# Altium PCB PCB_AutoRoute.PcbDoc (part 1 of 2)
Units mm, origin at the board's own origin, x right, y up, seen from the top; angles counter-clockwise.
Board outline 100 x 100 mm, 4 copper layers (Top Layer, AGND, PWR, Bottom Layer), stack 1.747 mm thick; 183 components, 95 nets, 503 pads, 230 vias.
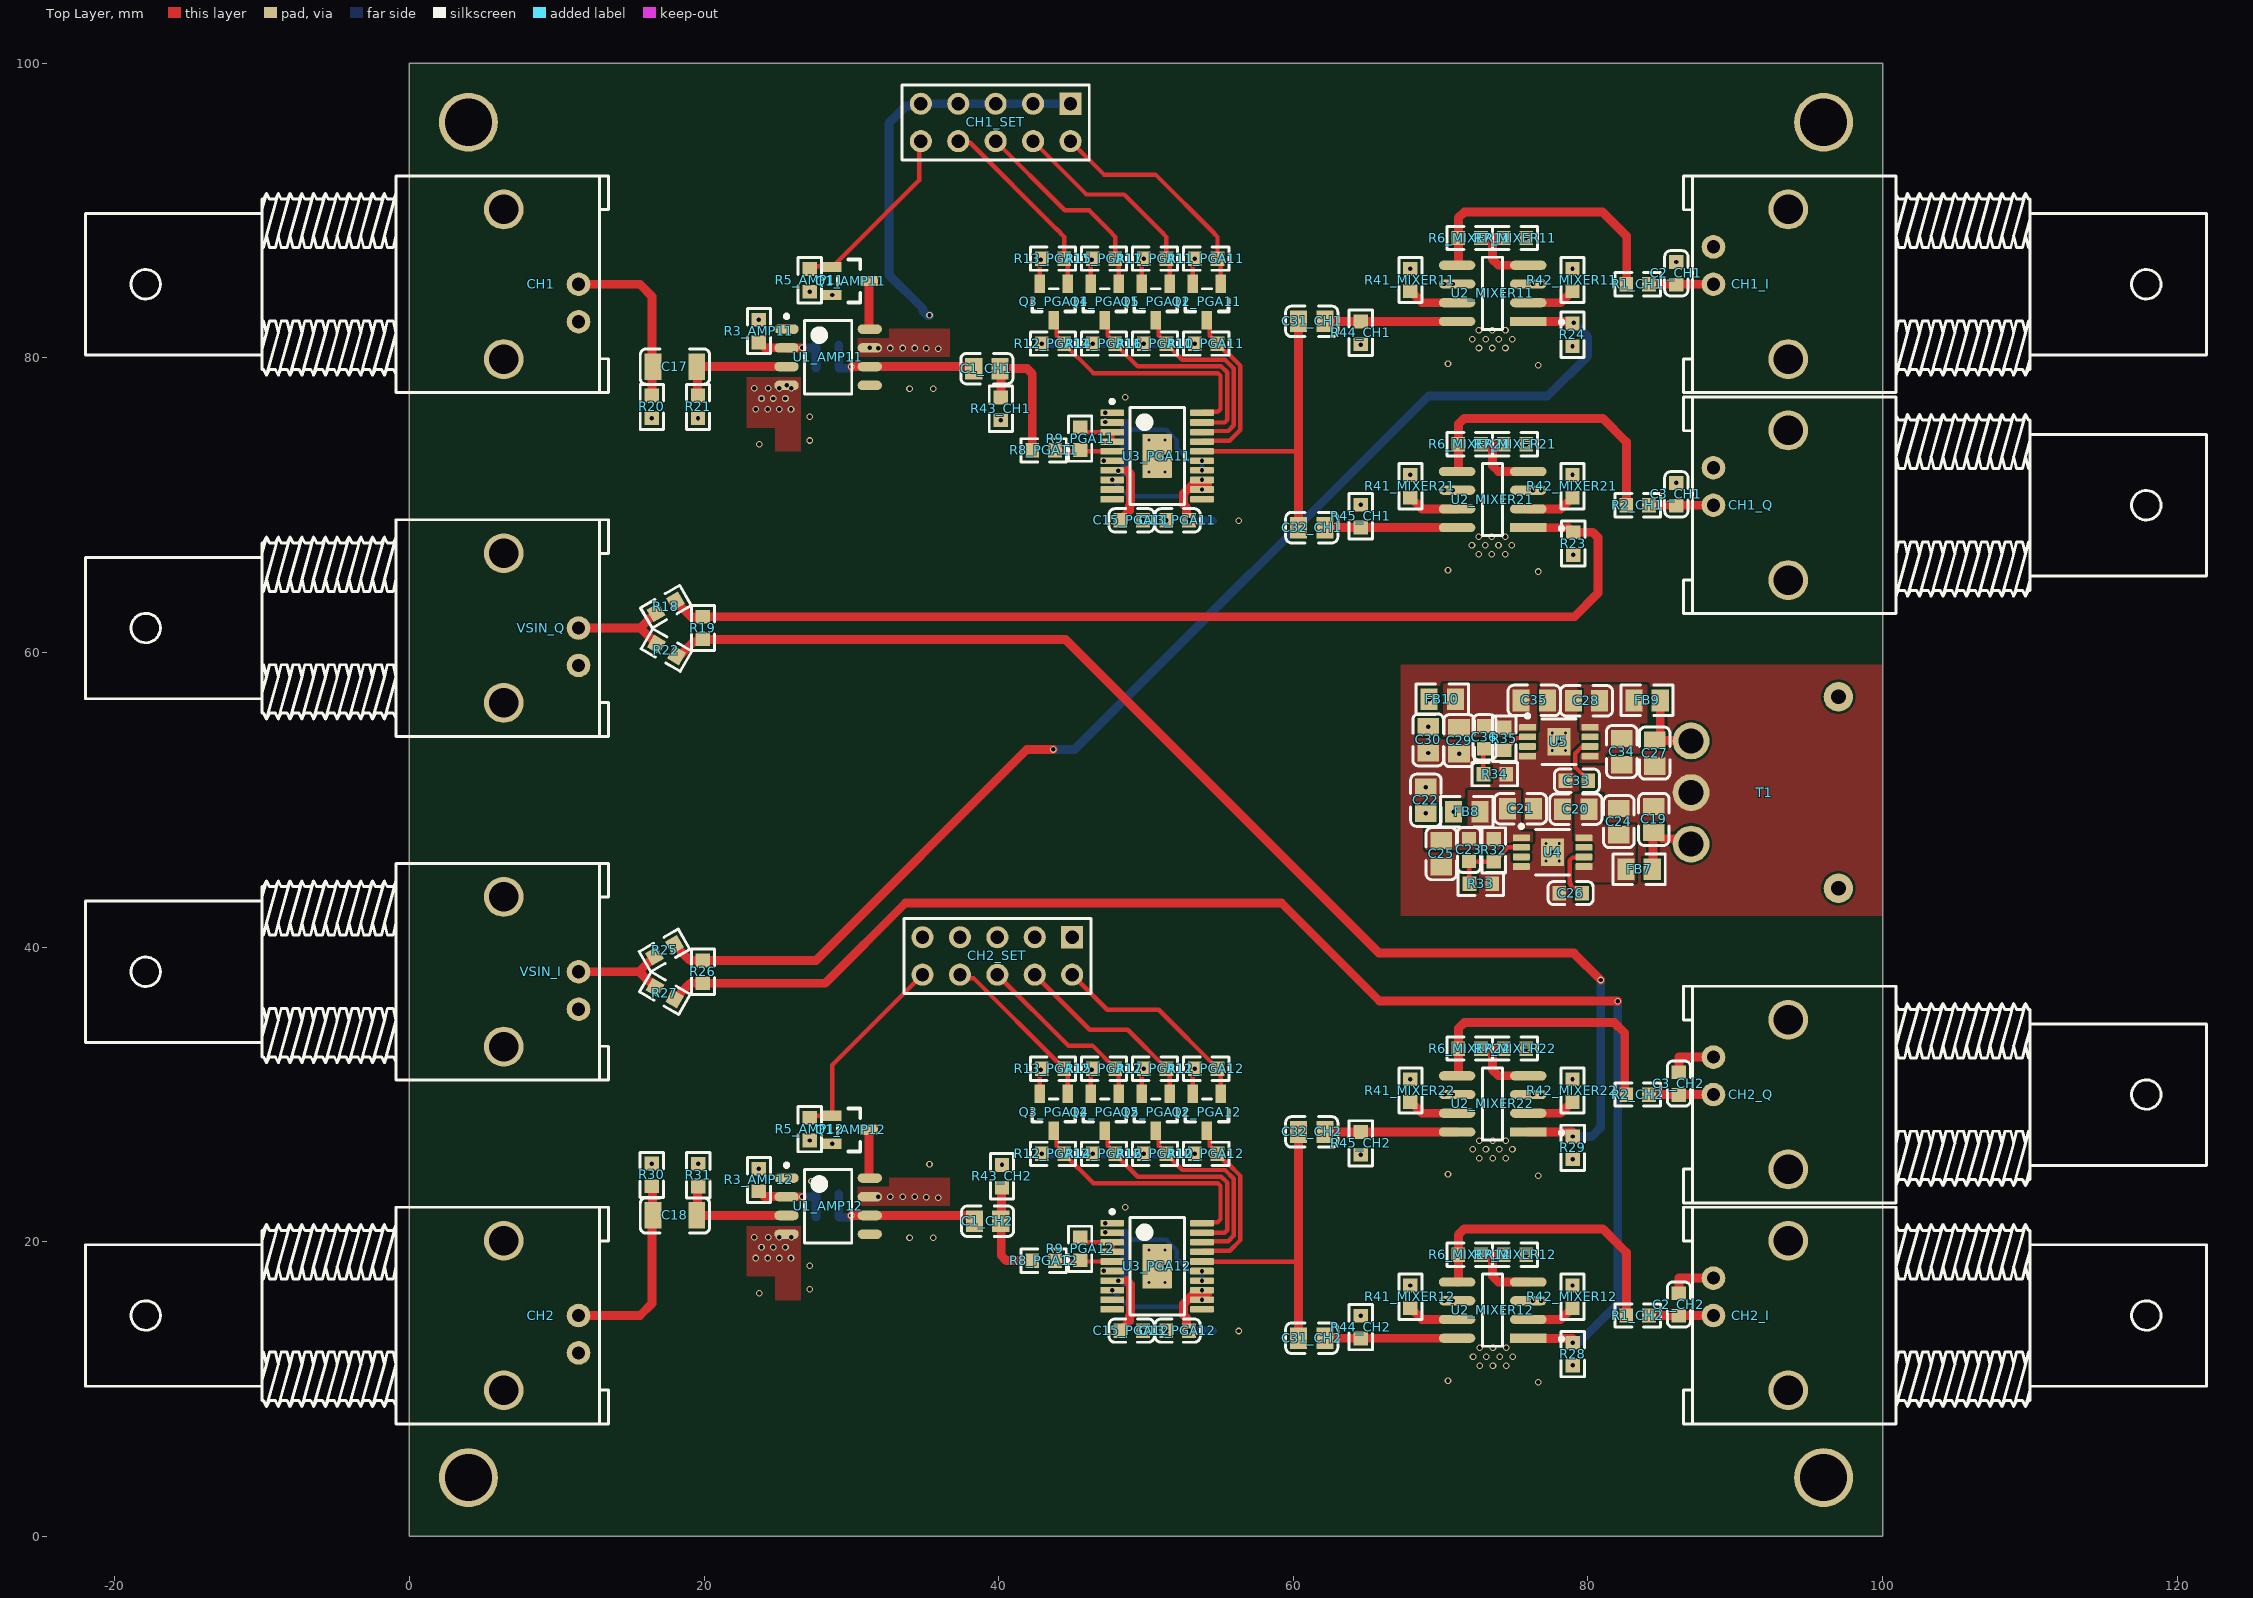
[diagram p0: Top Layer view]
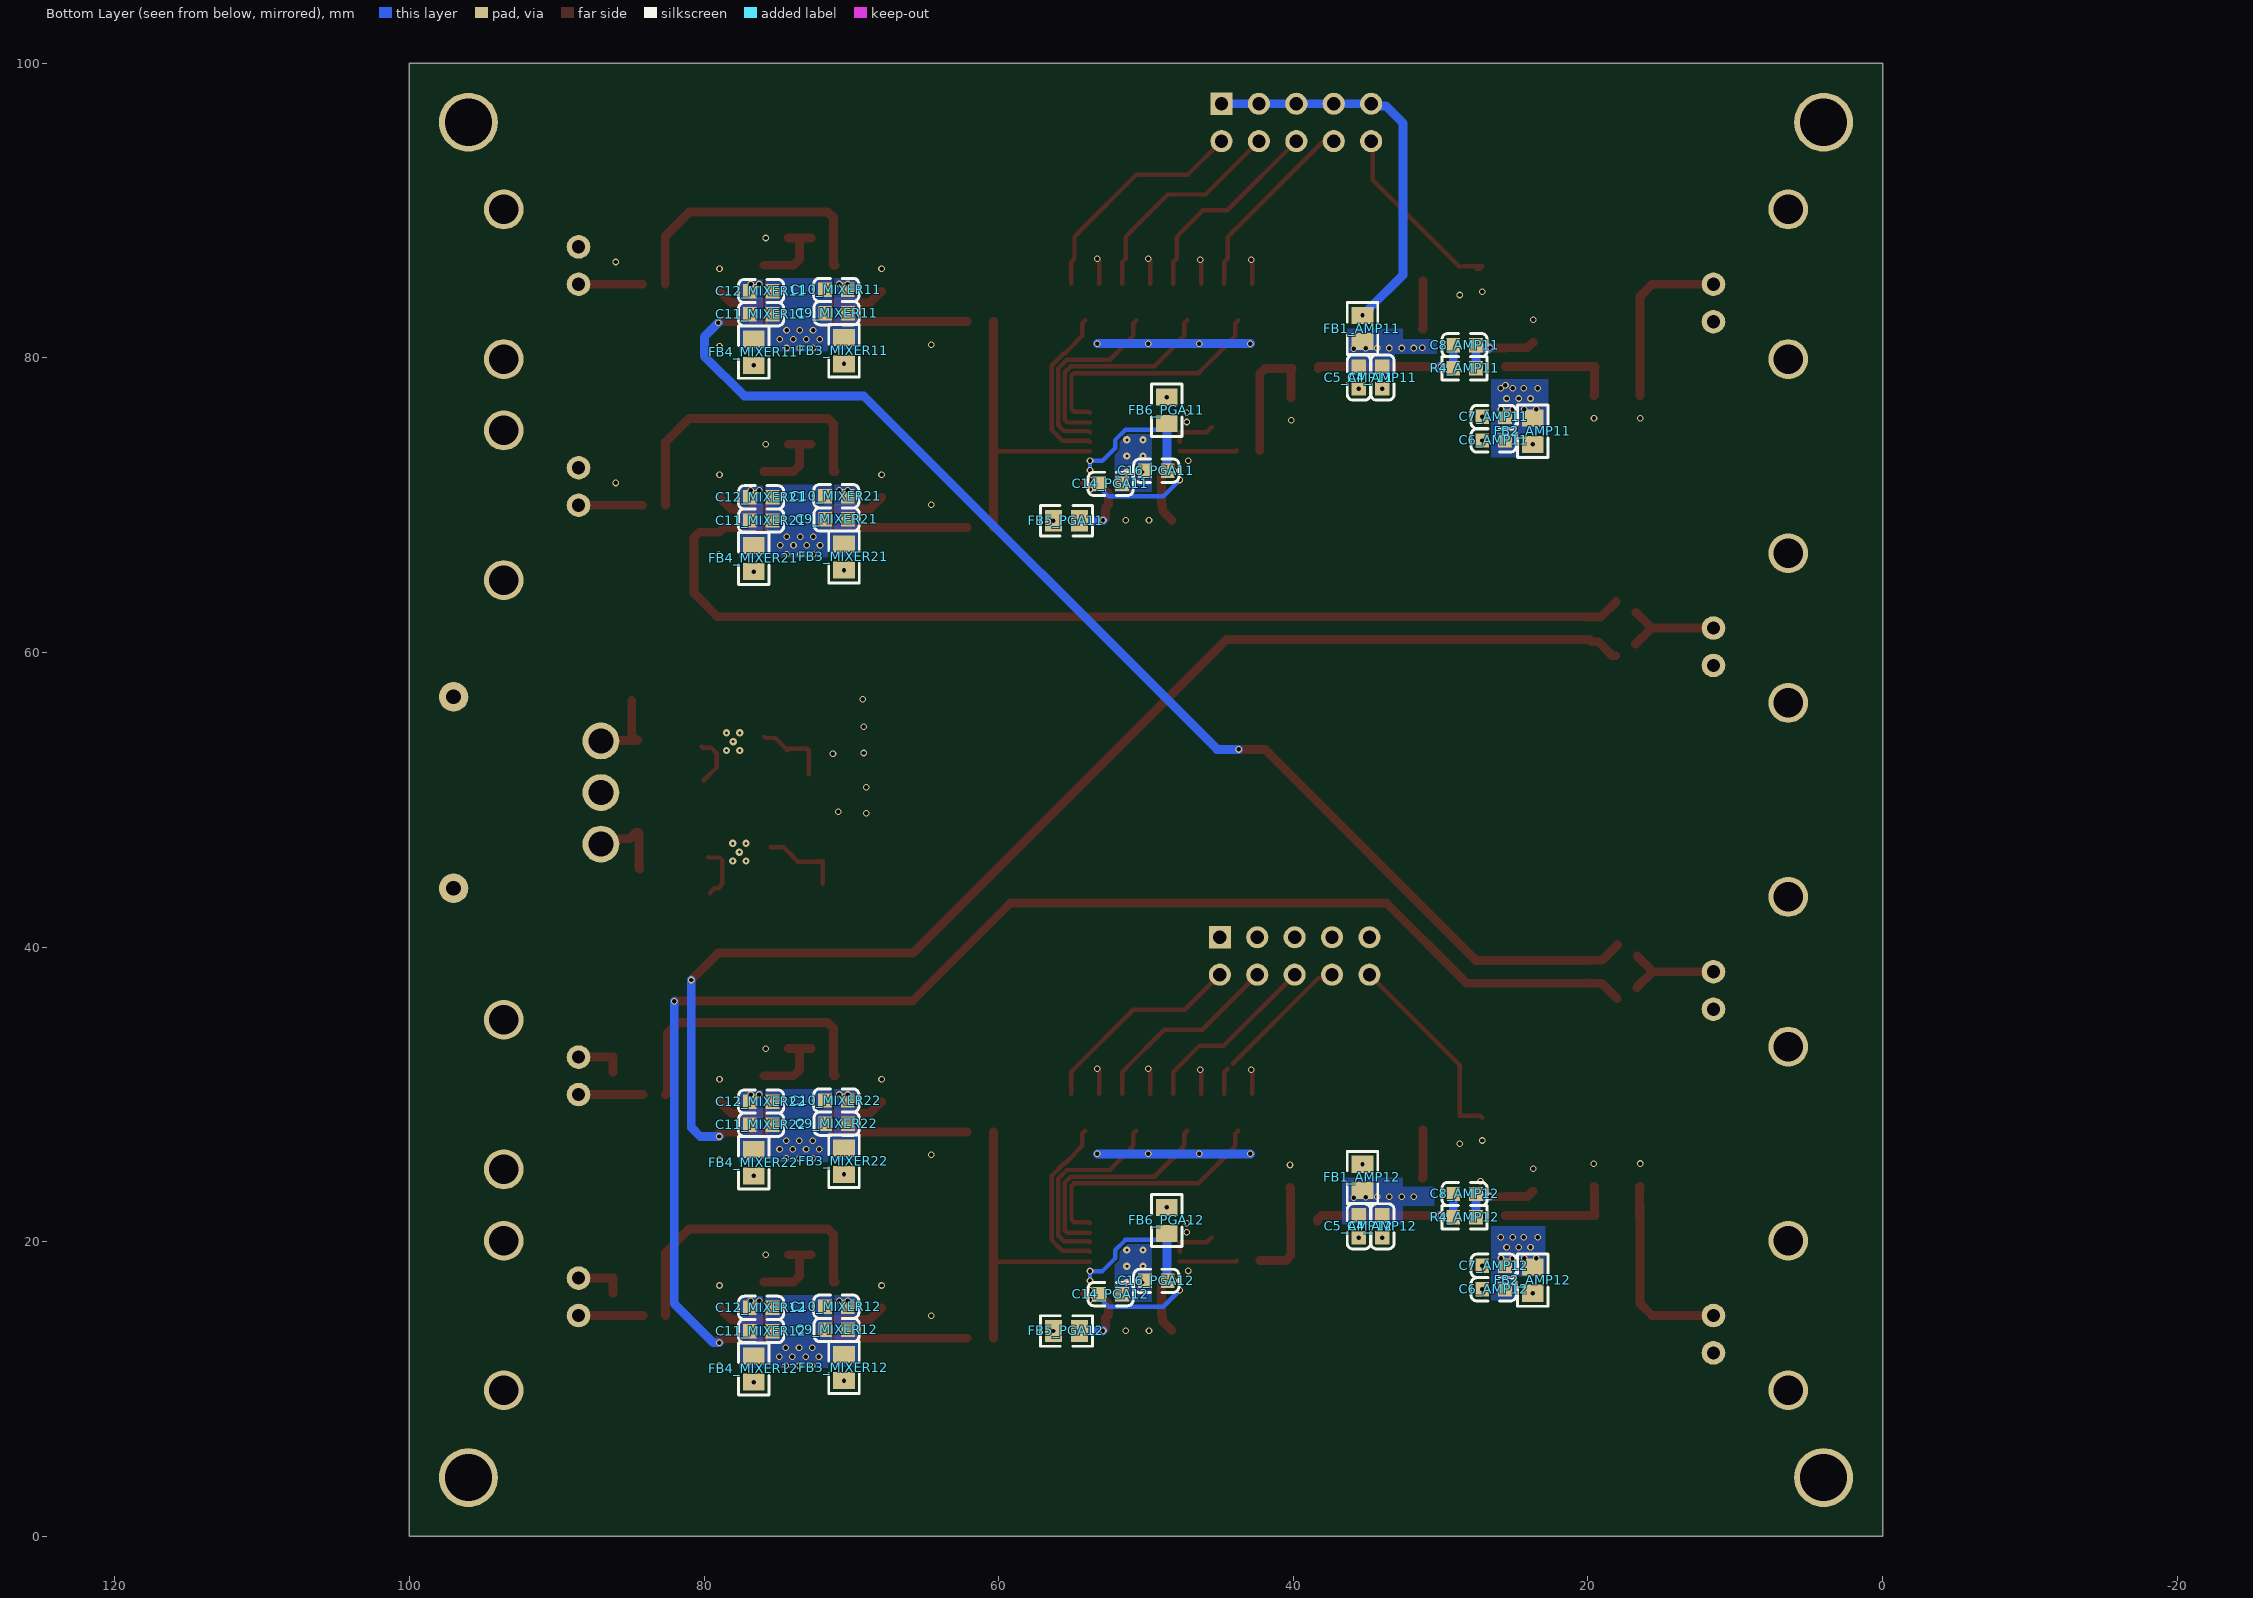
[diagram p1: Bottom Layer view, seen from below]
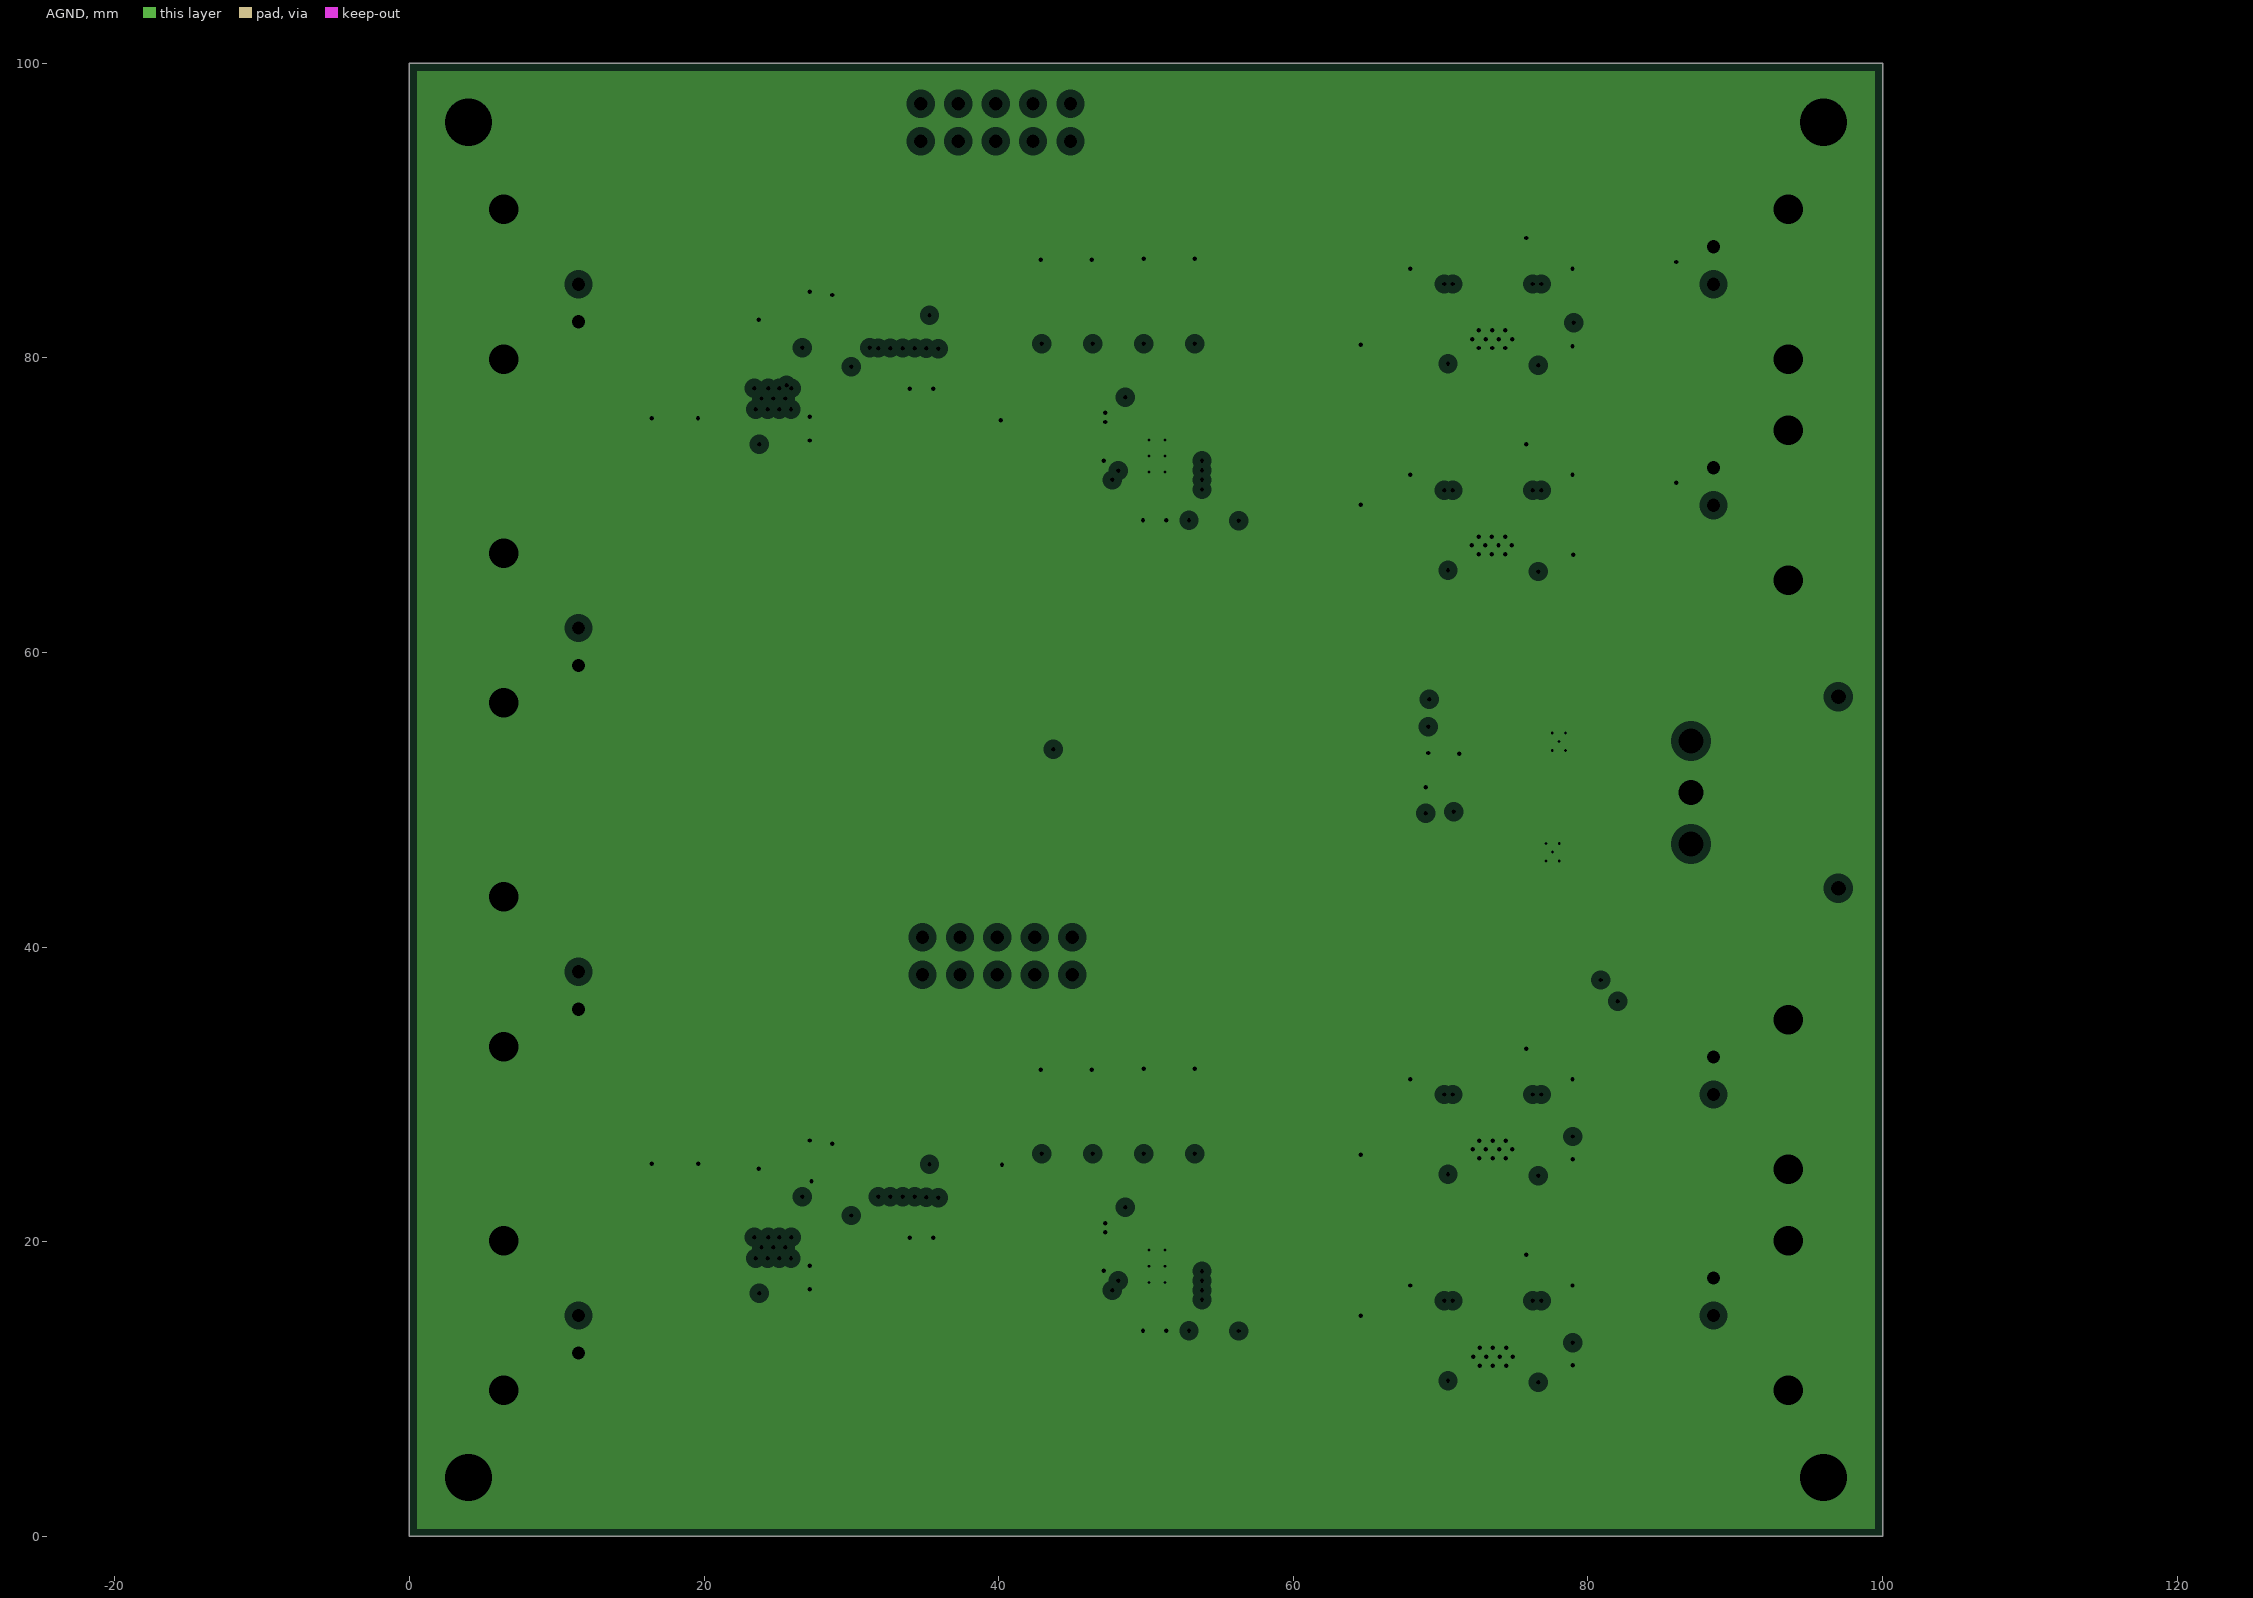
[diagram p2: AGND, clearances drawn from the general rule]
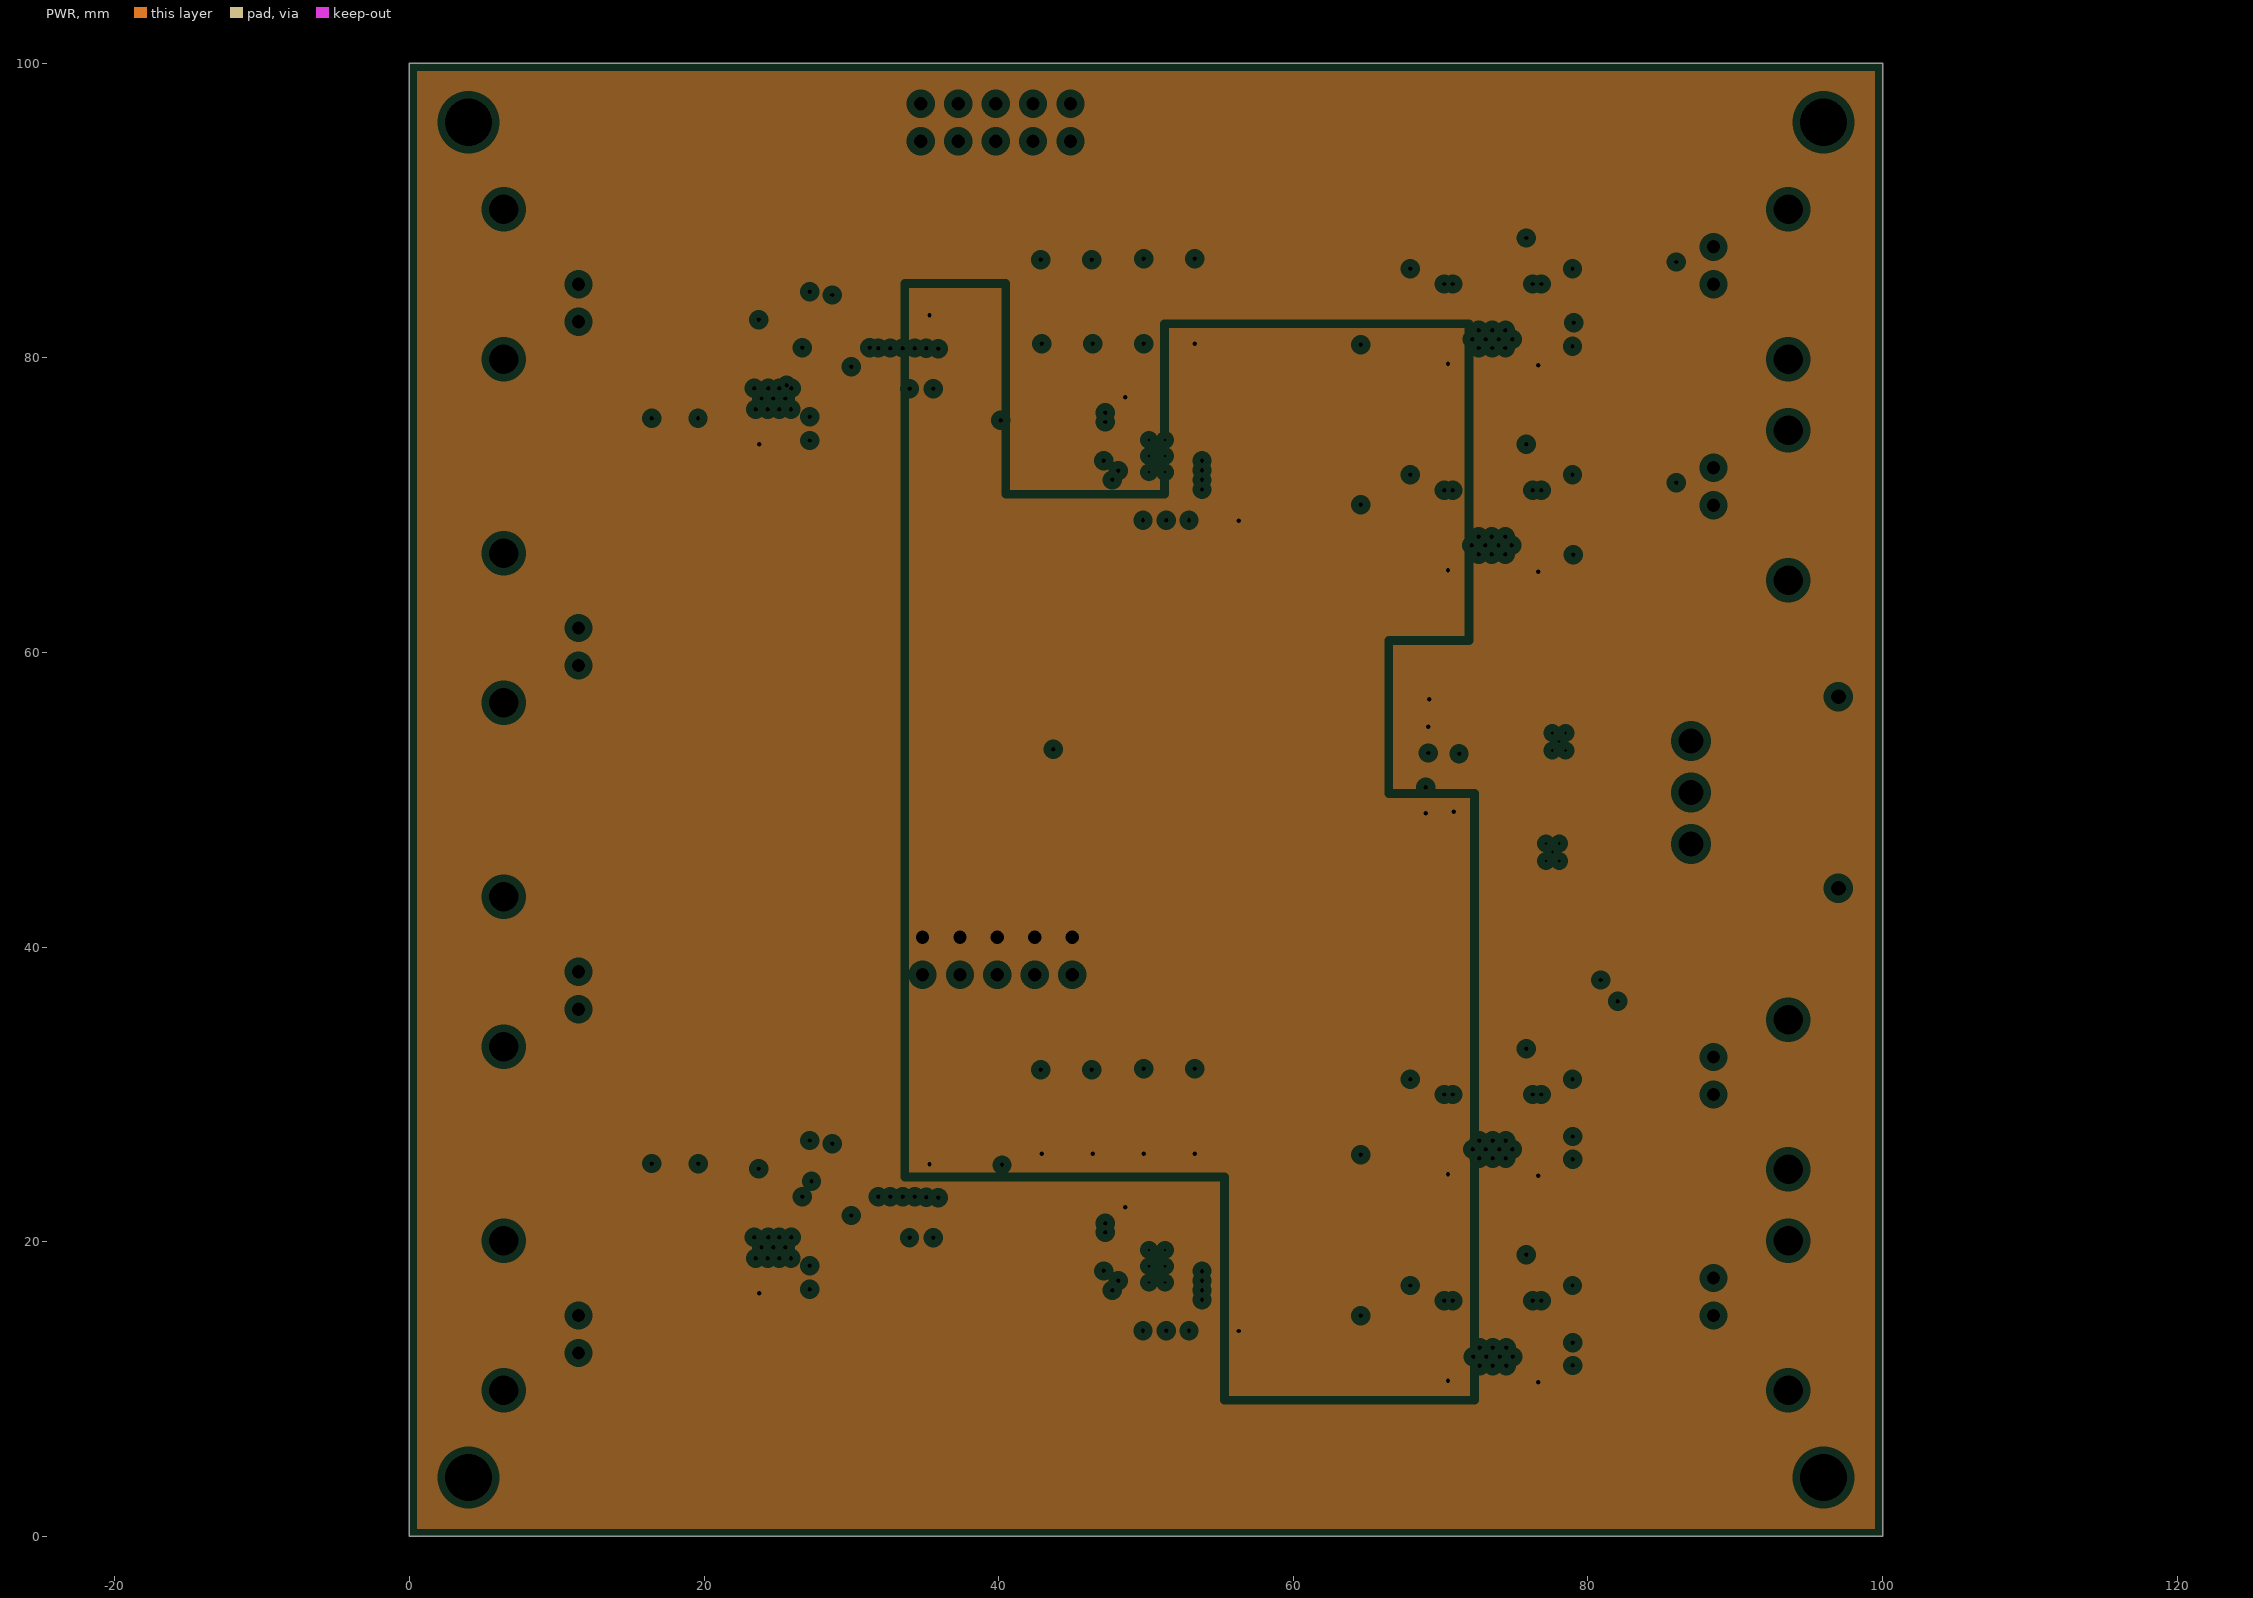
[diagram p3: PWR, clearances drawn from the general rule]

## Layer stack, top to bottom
Top Solder: solder mask 0.015, Solder Resist, Dk 3.5
Top Layer: signal copper 0.035
Dielectric 2: prepreg 0.0711, PP-006, Dk 4.1
AGND: plane copper 0.0175, net AGND
Dielectric 1: dielectric 1.5, FR-4, Dk 4.8
PWR: plane copper 0.0175, net +AVEE_5P5V
Dielectric 3: prepreg 0.0711, PP-006, Dk 4.1
Bottom Layer: signal copper 0.035
Bottom Solder: solder mask 0.015, Solder Resist, Dk 3.5

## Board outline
0,0 0,100 100,100 100,0

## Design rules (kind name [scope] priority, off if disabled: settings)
Clearance [All] p1: gap=0.152 ignorepadtopadclearanceinfootprint=FALSE
MinimumSolderMaskSliver [All] p1: minsoldermaskwidth=0.127
PlaneClearance [All] p1: clearance=0.508
PlaneConnect [All] p1: planeconnectstyle=Direct reliefexpansion=0.508 reliefentries=4 reliefconductorwidth=0.254 reliefairgap=0.254
PolygonConnect [All] p1: connectstyle=Direct reliefconductorwidth=0.254 reliefentries=4 polygonreliefangle="90 Angle" airgapwidth=0.254
RoomDefinition MIXER21 [InComponentClass('MIXER21')] p1: confinementstyle=ConfineIn formatcopy=TRUE lockcomponents=FALSE outline 81.35,77.52 66,77.52 66,63.52 81.35,63.52
RoomDefinition MIXER22 [InComponentClass('MIXER22')] p2: confinementstyle=ConfineIn formatcopy=TRUE lockcomponents=FALSE outline 81.35,36.5 66,36.5 66,22.5 81.35,22.5
RoomDefinition MIXER12 [InComponentClass('MIXER12')] p3: confinementstyle=ConfineIn formatcopy=TRUE lockcomponents=FALSE outline 81.35,22.5 66,22.5 66,8.5 81.35,8.5
RoomDefinition PGA11 [InComponentClass('PGA11')] p4: confinementstyle=ConfineIn formatcopy=TRUE lockcomponents=FALSE outline 41.4,66.791 57.893,66.791 57.893,88.216 41.4,88.216
RoomDefinition PWR [InComponentClass('PWR')] p5: confinementstyle=ConfineIn formatcopy=TRUE lockcomponents=FALSE outline 100.242,59.125 67.325,59.125 67.325,42.125 100.242,42.125
RoomDefinition PGA12 [InComponentClass('PGA12')] p6: confinementstyle=ConfineIn formatcopy=TRUE lockcomponents=FALSE outline 41.4,11.791 57.893,11.791 57.893,33.216 41.4,33.216
RoomDefinition MIXER11 [InComponentClass('MIXER11')] p7: confinementstyle=ConfineIn formatcopy=TRUE lockcomponents=FALSE outline 81.35,91.52 66,91.52 66,77.52 81.35,77.52
RoomDefinition AMP12 [InComponentClass('AMP12')] p8: confinementstyle=ConfineIn formatcopy=TRUE lockcomponents=FALSE outline 22.3,15.453 36.95,15.453 36.95,29.553 22.3,29.553
RoomDefinition AMP11 [InComponentClass('AMP11')] p9: confinementstyle=ConfineIn formatcopy=TRUE lockcomponents=FALSE outline 22.3,73.075 36.95,73.075 36.95,87.175 22.3,87.175
RoutingVias [All] p1: holewidth=0.3 width=0.45 viastyle="Through Hole" minholewidth=0.3 minwidth=0.4 maxholewidth=0.3 maxwidth=0.6
SilkToSilkClearance [All] p1: silktosilkclearance=0.127
SilkToSolderMaskClearance [IsPad] p1: minsilkscreentomaskgap=0.152 clearancetoexposedcopper=TRUE
SolderMaskExpansion [All] p1: expansion=0.102 istentingtop=FALSE
SupplyNets "Schematic Supply Nets_2" [InNet('+AVEE_5P5V')] p1: voltage=0.000
SupplyNets "Schematic Supply Nets_1" [InNet('+AVDD_5P5V')] p2: voltage=0.000
SupplyNets "Schematic Supply Nets" [InNet('AGND')] p3: voltage=0.000
Width [All] p1: maxlimit=25.4 minlimit=0.127 preferedwidth=0.254
25 further rules are at their usual default settings.

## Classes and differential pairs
component class PWR: C19 C20 C21 C22 C23 C24 C25 C26 C27 C28 C29 C30 C33 C34 C35 C36 FB7 FB8 FB9 FB10 R32 R33 R34 R35 T1 U4 U5
channel class THS7001_PGA: PGA11 PGA12
channel class OPA847_LNA: AMP11 AMP12
channel class Analog_Channel: CH1 CH2
channel class AD835_Mixer: MIXER11 MIXER12 MIXER21 MIXER22
net class CH2_CONT_BIT[0..4]: CH2_CONT_BIT0 CH2_CONT_BIT1 CH2_CONT_BIT2 CH2_CONT_BIT3 CH2_CONT_BIT4
net class CH1_CONT_BIT[0..4]: CH1_CONT_BIT0 CH1_CONT_BIT1 CH1_CONT_BIT2 CH1_CONT_BIT3 CH1_CONT_BIT4
component class PGA12: C13_PGA12 C14_PGA12 C15_PGA12 C16_PGA12 FB5_PGA12 FB6_PGA12 Q2_PGA12 Q3_PGA12 Q4_PGA12 Q5_PGA12 R8_PGA12 R9_PGA12 R10_PGA12 R11_PGA12 R12_PGA12 R13_PGA12 R14_PGA12 R15_PGA12 R16_PGA12 R17_PGA12 U3_PGA12
component class PGA11: C13_PGA11 C14_PGA11 C15_PGA11 C16_PGA11 FB5_PGA11 FB6_PGA11 Q2_PGA11 Q3_PGA11 Q4_PGA11 Q5_PGA11 R8_PGA11 R9_PGA11 R10_PGA11 R11_PGA11 R12_PGA11 R13_PGA11 R14_PGA11 R15_PGA11 R16_PGA11 R17_PGA11 U3_PGA11
component class MIXER22: C9_MIXER22 C10_MIXER22 C11_MIXER22 C12_MIXER22 FB3_MIXER22 FB4_MIXER22 R6_MIXER22 R7_MIXER22 R41_MIXER22 R42_MIXER22 U2_MIXER22
component class MIXER21: C9_MIXER21 C10_MIXER21 C11_MIXER21 C12_MIXER21 FB3_MIXER21 FB4_MIXER21 R6_MIXER21 R7_MIXER21 R41_MIXER21 R42_MIXER21 U2_MIXER21
component class MIXER12: C9_MIXER12 C10_MIXER12 C11_MIXER12 C12_MIXER12 FB3_MIXER12 FB4_MIXER12 R6_MIXER12 R7_MIXER12 R41_MIXER12 R42_MIXER12 U2_MIXER12
component class MIXER11: C9_MIXER11 C10_MIXER11 C11_MIXER11 C12_MIXER11 FB3_MIXER11 FB4_MIXER11 R6_MIXER11 R7_MIXER11 R41_MIXER11 R42_MIXER11 U2_MIXER11
component class CH2: C1_CH2 C2_CH2 C3_CH2 C31_CH2 C32_CH2 R1_CH2 R2_CH2 R43_CH2 R44_CH2 R45_CH2
component class CH1: C1_CH1 C2_CH1 C3_CH1 C31_CH1 C32_CH1 R1_CH1 R2_CH1 R43_CH1 R44_CH1 R45_CH1
component class Analog_Channel_Test: C17 C18 CH1 CH1_I CH1_Q CH1_SET CH2 CH2_I CH2_Q CH2_SET R18 R19 R20 R21 R22 R23 R24 R25 R26 R27 R28 R29 R30 R31 VSIN_I VSIN_Q
component class AMP12: C4_AMP12 C5_AMP12 C6_AMP12 C7_AMP12 C8_AMP12 FB1_AMP12 FB2_AMP12 Q1_AMP12 R3_AMP12 R4_AMP12 R5_AMP12 U1_AMP12
component class AMP11: C4_AMP11 C5_AMP11 C6_AMP11 C7_AMP11 C8_AMP11 FB1_AMP11 FB2_AMP11 Q1_AMP11 R3_AMP11 R4_AMP11 R5_AMP11 U1_AMP11

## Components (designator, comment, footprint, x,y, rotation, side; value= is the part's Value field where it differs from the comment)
C1_CH1 "100nF" 0805_C 39.2,79.275 r0 top (schematic designator C1)
C1_CH2 "100nF" 0805_C 39.25,21.4 r0 top (schematic designator C1)
C2_CH1 "10nF" 0603_C 86,85.745 r270 top (schematic designator C2)
C2_CH2 "10nF" 0603_C 86.175,15.745 r270 top (schematic designator C2)
C3_CH1 "10nF" 0603_C 86,70.745 r270 top (schematic designator C3)
C3_CH2 "10nF" 0603_C 86.175,30.745 r270 top (schematic designator C3)
C4_AMP11 "100nF" 0603_C 33.95,78.672 r90 bottom (schematic designator C4)
C4_AMP12 "100nF" 0603_C 33.95,21.05 r90 bottom (schematic designator C4)
C5_AMP11 "10nF" 0603_C 35.55,78.672 r90 bottom (schematic designator C5)
C5_AMP12 "10nF" 0603_C 35.55,21.05 r90 bottom (schematic designator C5)
C6_AMP11 "100nF" 0603_C 26.4,74.397 r180 bottom (schematic designator C6)
C6_AMP12 "100nF" 0603_C 26.4,16.775 r180 bottom (schematic designator C6)
C7_AMP11 "10nF" 0603_C 26.4,75.997 r180 bottom (schematic designator C7)
C7_AMP12 "10nF" 0603_C 26.4,18.375 r180 bottom (schematic designator C7)
C8_AMP11 "10pF" 0603_C 28.375,80.872 r0 bottom (schematic designator C8)
C8_AMP12 "10pF" 0603_C 28.375,23.25 r0 bottom (schematic designator C8)
C9_MIXER11 "100nF" 0603_C 71,83.04 r180 bottom (schematic designator C9)
C9_MIXER12 "100nF" 0603_C 71,14.02 r180 bottom (schematic designator C9)
C9_MIXER21 "100nF" 0603_C 71,69.04 r180 bottom (schematic designator C9)
C9_MIXER22 "100nF" 0603_C 71,28.02 r180 bottom (schematic designator C9)
C10_MIXER11 "10nF" 0603_C 71.02,84.615 r180 bottom (schematic designator C10)
C10_MIXER12 "10nF" 0603_C 71.02,15.595 r180 bottom (schematic designator C10)
C10_MIXER21 "10nF" 0603_C 71.02,70.615 r180 bottom (schematic designator C10)
C10_MIXER22 "10nF" 0603_C 71.02,29.595 r180 bottom (schematic designator C10)
C11_MIXER11 "100nF" 0603_C 76.125,82.965 r0 bottom (schematic designator C11)
C11_MIXER12 "100nF" 0603_C 76.125,13.945 r0 bottom (schematic designator C11)
C11_MIXER21 "100nF" 0603_C 76.125,68.965 r0 bottom (schematic designator C11)
C11_MIXER22 "100nF" 0603_C 76.125,27.945 r0 bottom (schematic designator C11)
C12_MIXER11 "10nF" 0603_C 76.125,84.54 r0 bottom (schematic designator C12)
C12_MIXER12 "10nF" 0603_C 76.125,15.52 r0 bottom (schematic designator C12)
C12_MIXER21 "10nF" 0603_C 76.125,70.54 r0 bottom (schematic designator C12)
C12_MIXER22 "10nF" 0603_C 76.125,29.52 r0 bottom (schematic designator C12)
C13_PGA11 "100nF" 0603_C 52.15,68.975 r0 top (schematic designator C13)
C13_PGA12 "100nF" 0603_C 52.15,13.975 r0 top (schematic designator C13)
C14_PGA11 "10nF" 0603_C 52.4,71.45 r0 bottom (schematic designator C14)
C14_PGA12 "10nF" 0603_C 52.4,16.45 r0 bottom (schematic designator C14)
C15_PGA11 "100nF" 0603_C 49.025,68.975 r180 top (schematic designator C15)
C15_PGA12 "100nF" 0603_C 49.025,13.975 r180 top (schematic designator C15)
C16_PGA11 "10nF" 0603_C 49.3,72.35 r180 bottom (schematic designator C16)
C16_PGA12 "10nF" 0603_C 49.3,17.35 r180 bottom (schematic designator C16)
C17 "330nF" 1206_C 18.025,79.412 r0 top
C18 "330nF" 1206_C 18.025,21.79 r0 top
C19 "10uF" 0805_C 84.475,48.675 r270 top
C20 "10uF" 0805_C 79.175,49.375 r0 top
C21 "10uF" 0805_C 75.425,49.4 r180 top
C22 "10uF" 0805_C 69,49.975 r270 top
C23 "10nF" 0603_C 71.925,46.6 r90 top
C24 "10uF" 0805_C 82.1,48.525 r270 top
C25 "10uF" 0805_C 70.05,46.35 r90 top
C26 "100nF" 0603_C 78.825,43.675 r0 top
C27 "10uF" 0805_C 84.525,53.175 r270 top
C28 "10uF" 0805_C 79.9,56.725 r180 top
C29 "10uF" 0805_C 71.25,54.025 r270 top
C30 "10uF" 0805_C 69.15,54.075 r270 top
C31_CH1 "100nF" 0805_C 61.25,82.48 r0 top (schematic designator C31)
C31_CH2 "100nF" 0805_C 61.25,13.46 r0 top (schematic designator C31)
C32_CH1 "100nF" 0805_C 61.25,68.48 r0 top (schematic designator C32)
C32_CH2 "100nF" 0805_C 61.25,27.46 r0 top (schematic designator C32)
C33 "100nF" 0603_C 79.25,51.3 r0 top
C34 "10uF" 0805_C 82.3,53.275 r90 top
C35 "10uF" 0805_C 76.35,56.75 r180 top
C36 "10nF" 0603_C 72.975,54.25 r90 top
CH1 "BNC" BNC-TYCO_1-1337542-0 6,85 r180 top
CH1_I "BNC" BNC-TYCO_1-1337542-0 94,85 r0 top
CH1_Q "BNC" BNC-TYCO_1-1337542-0 94,70 r0 top
CH1_SET "Pin HDR2X5" "Pin HDR2X5/2.54mm-S" 44.877,97.255 r180 top
CH2 "BNC" BNC-TYCO_1-1337542-0 6,15 r180 top
CH2_I "BNC" BNC-TYCO_1-1337542-0 94,15 r0 top
CH2_Q "BNC" BNC-TYCO_1-1337542-0 94,30 r0 top
CH2_SET "Pin HDR2X5" "Pin HDR2X5/2.54mm-S" 44.99,40.675 r180 top
FB1_AMP11 "Bead" 0805_L 35.305,81.997 r270 bottom (schematic designator FB1)
FB1_AMP12 "Bead" 0805_L 35.305,24.375 r270 bottom (schematic designator FB1)
FB2_AMP11 "Bead" 0805_L 23.75,75.022 r90 bottom (schematic designator FB2)
FB2_AMP12 "Bead" 0805_L 23.75,17.4 r90 bottom (schematic designator FB2)
FB3_MIXER11 "Bead" 0805_L 70.5,80.49 r90 bottom (schematic designator FB3)
FB3_MIXER12 "Bead" 0805_L 70.5,11.47 r90 bottom (schematic designator FB3)
FB3_MIXER21 "Bead" 0805_L 70.5,66.49 r90 bottom (schematic designator FB3)
FB3_MIXER22 "Bead" 0805_L 70.5,25.47 r90 bottom (schematic designator FB3)
FB4_MIXER11 "Bead" 0805_L 76.625,80.39 r90 bottom (schematic designator FB4)
FB4_MIXER12 "Bead" 0805_L 76.625,11.37 r90 bottom (schematic designator FB4)
FB4_MIXER21 "Bead" 0805_L 76.625,66.39 r90 bottom (schematic designator FB4)
FB4_MIXER22 "Bead" 0805_L 76.625,25.37 r90 bottom (schematic designator FB4)
FB5_PGA11 "Bead" 0805_L 55.4,68.95 r180 bottom (schematic designator FB5)
FB5_PGA12 "Bead" 0805_L 55.4,13.95 r180 bottom (schematic designator FB5)
FB6_PGA11 "Bead" 0805_L 48.6,76.45 r270 bottom (schematic designator FB6)
FB6_PGA12 "Bead" 0805_L 48.6,21.45 r270 bottom (schematic designator FB6)
FB7 "Bead" 0805_L 83.475,45.3 r0 top
FB8 "Bead" 0805_L 71.775,49.2 r0 top
FB9 "Bead" 0805_L 84.015,56.75 r180 top
FB10 "Bead" 0805_L 70.11,56.825 r0 top
Q1_AMP11 "2N7002" SOT-23(SOT-23-3) 29.95,85.222 r180 top (schematic designator Q1)
Q1_AMP12 "2N7002" SOT-23(SOT-23-3) 29.95,27.6 r180 top (schematic designator Q1)
Q2_PGA11 "2N7002" SOT-23(SOT-23-3) 54.132,83.798 r90 top (schematic designator Q2)
Q2_PGA12 "2N7002" SOT-23(SOT-23-3) 54.132,28.798 r90 top (schematic designator Q2)
Q3_PGA11 "2N7002" SOT-23(SOT-23-3) 43.732,83.798 r90 top (schematic designator Q3)
Q3_PGA12 "2N7002" SOT-23(SOT-23-3) 43.732,28.798 r90 top (schematic designator Q3)
Q4_PGA11 "2N7002" SOT-23(SOT-23-3) 47.199,83.798 r90 top (schematic designator Q4)
Q4_PGA12 "2N7002" SOT-23(SOT-23-3) 47.199,28.798 r90 top (schematic designator Q4)
Q5_PGA11 "2N7002" SOT-23(SOT-23-3) 50.665,83.798 r90 top (schematic designator Q5)
Q5_PGA12 "2N7002" SOT-23(SOT-23-3) 50.665,28.798 r90 top (schematic designator Q5)
R1_CH1 "10kΩ" 0603_R 83.375,85 r180 top (schematic designator R1)
R1_CH2 "10kΩ" 0603_R 83.375,15 r180 top (schematic designator R1)
R2_CH1 "10kΩ" 0603_R 83.375,70 r180 top (schematic designator R2)
R2_CH2 "10kΩ" 0603_R 83.375,30 r180 top (schematic designator R2)
R3_AMP11 "100Ω" 0603_R 23.725,81.822 r270 top (schematic designator R3)
R3_AMP12 "100Ω" 0603_R 23.725,24.2 r270 top (schematic designator R3)
R4_AMP11 "910Ω" 0603_R 28.375,79.297 r0 bottom (schematic designator R4)
R4_AMP12 "910Ω" 0603_R 28.375,21.675 r0 bottom (schematic designator R4)
R5_AMP11 "10kΩ" 0603_R 27.175,85.272 r90 top (schematic designator R5)
R5_AMP12 "10kΩ" 0603_R 27.175,27.65 r90 top (schematic designator R5)
R6_MIXER11 "2kΩ" 0603_R 71.975,88.14 r180 top (schematic designator R6)
R6_MIXER12 "2kΩ" 0603_R 71.975,19.12 r180 top (schematic designator R6)
R6_MIXER21 "2kΩ" 0603_R 71.975,74.14 r180 top (schematic designator R6)
R6_MIXER22 "2kΩ" 0603_R 71.975,33.12 r180 top (schematic designator R6)
R7_MIXER11 "200Ω" 0603_R 75.05,88.14 r180 top (schematic designator R7)
R7_MIXER12 "200Ω" 0603_R 75.05,19.12 r180 top (schematic designator R7)
R7_MIXER21 "200Ω" 0603_R 75.05,74.14 r180 top (schematic designator R7)
R7_MIXER22 "200Ω" 0603_R 75.05,33.12 r180 top (schematic designator R7)
R8_PGA11 "100Ω" 0603_R 43.052,73.723 r0 top (schematic designator R8)
R8_PGA12 "100Ω" 0603_R 43.052,18.723 r0 top (schematic designator R8)
R9_PGA11 "100Ω" 0603_R 45.527,74.523 r90 top (schematic designator R9)
R9_PGA12 "100Ω" 0603_R 45.527,19.523 r90 top (schematic designator R9)
R10_PGA11 "10kΩ" 0603_R 54.084,80.973 r180 top (schematic designator R10)
R10_PGA12 "10kΩ" 0603_R 54.084,25.973 r180 top (schematic designator R10)
R11_PGA11 "10kΩ" 0603_R 54.084,86.743 r0 top (schematic designator R11)
R11_PGA12 "10kΩ" 0603_R 54.084,31.743 r0 top (schematic designator R11)
R12_PGA11 "10kΩ" 0603_R 43.684,80.973 r180 top (schematic designator R12)
R12_PGA12 "10kΩ" 0603_R 43.684,25.973 r180 top (schematic designator R12)
R13_PGA11 "10kΩ" 0603_R 43.684,86.743 r0 top (schematic designator R13)
R13_PGA12 "10kΩ" 0603_R 43.684,31.743 r0 top (schematic designator R13)
R14_PGA11 "10kΩ" 0603_R 47.151,80.973 r180 top (schematic designator R14)
R14_PGA12 "10kΩ" 0603_R 47.151,25.973 r180 top (schematic designator R14)
R15_PGA11 "10kΩ" 0603_R 47.151,86.743 r0 top (schematic designator R15)
R15_PGA12 "10kΩ" 0603_R 47.151,31.743 r0 top (schematic designator R15)
R16_PGA11 "10kΩ" 0603_R 50.617,80.973 r180 top (schematic designator R16)
R16_PGA12 "10kΩ" 0603_R 50.617,25.973 r180 top (schematic designator R16)
R17_PGA11 "10kΩ" 0603_R 50.617,86.743 r0 top (schematic designator R17)
R17_PGA12 "10kΩ" 0603_R 50.617,31.743 r0 top (schematic designator R17)
R18 "49.9Ω" 0603_R 17.408,63.115 r210 top
R19 "49.9Ω" 0603_R 19.925,61.667 r270 top
R20 "49.9Ω" 0603_R 16.46,76.675 r90 top
R21 "10kΩ" 0603_R 19.59,76.675 r90 top
R22 "49.9Ω" 0603_R 17.45,60.175 r150 top
R23 "49.9Ω" 0603_R 79,67.4 r90 top
R24 "49.9Ω" 0603_R 78.95,81.57 r90 top
R25 "49.9Ω" 0603_R 17.317,39.785 r210 top
R26 "49.9Ω" 0603_R 19.925,38.333 r270 top
R27 "49.9Ω" 0603_R 17.342,36.885 r150 top
R28 "49.9Ω" 0603_R 78.975,12.38 r90 top
R29 "49.9Ω" 0603_R 78.975,26.38 r90 top
R30 "49.9Ω" 0603_R 16.45,24.545 r270 top
R31 "10kΩ" 0603_R 19.6,24.525 r270 top
R32 "91kΩ" 0603_R 73.6,46.575 r90 top
R33 "10kΩ" 0603_R 72.725,44.3 r180 top
R34 "10kΩ" 0603_R 73.675,51.75 r180 top
R35 "91kΩ" 0603_R 74.325,54.15 r90 top
R41_MIXER11 "200Ω" 0603_R 67.95,85.29 r270 top (schematic designator R41)
R41_MIXER12 "200Ω" 0603_R 67.95,16.27 r270 top (schematic designator R41)
R41_MIXER21 "200Ω" 0603_R 67.95,71.29 r270 top (schematic designator R41)
R41_MIXER22 "200Ω" 0603_R 67.95,30.27 r270 top (schematic designator R41)
R42_MIXER11 "200Ω" 0603_R 78.95,85.29 r270 top (schematic designator R42)
R42_MIXER12 "200Ω" 0603_R 78.95,16.27 r270 top (schematic designator R42)
R42_MIXER21 "200Ω" 0603_R 78.95,71.29 r270 top (schematic designator R42)
R42_MIXER22 "200Ω" 0603_R 78.95,30.27 r270 top (schematic designator R42)
R43_CH1 "10kΩ" 0603_R 40.15,76.55 r90 top (schematic designator R43)
R43_CH2 "10kΩ" 0603_R 40.225,24.45 r270 top (schematic designator R43)
R44_CH1 "10kΩ" 0603_R 64.575,81.705 r90 top (schematic designator R44)
R44_CH2 "10kΩ" 0603_R 64.575,14.21 r270 top (schematic designator R44)
R45_CH1 "10kΩ" 0603_R 64.575,69.255 r270 top (schematic designator R45)
R45_CH2 "10kΩ" 0603_R 64.575,26.685 r90 top (schematic designator R45)
T1 "MR30" MR30PW-M 87,47 r90 top
U1_AMP11 "OPA847" SOIC127P600X175-8M 28.425,80.047 r0 top (schematic designator U1)
U1_AMP12 "OPA847" SOIC127P600X175-8M 28.425,22.425 r0 top (schematic designator U1)
U2_MIXER11 "AD835ARZ" FP-R-8-IPC_A 73.534,84.385 r180 top (schematic designator U2)
U2_MIXER12 "AD835ARZ" FP-R-8-IPC_A 73.534,15.365 r180 top (schematic designator U2)
U2_MIXER21 "AD835ARZ" FP-R-8-IPC_A 73.534,70.385 r180 top (schematic designator U2)
U2_MIXER22 "AD835ARZ" FP-R-8-IPC_A 73.534,29.365 r180 top (schematic designator U2)
U3_PGA11 "THS7001CPWP" PWP0020D_M 50.752,73.343 r0 top (schematic designator U3)
U3_PGA12 "THS7001CPWP" PWP0020D_M 50.752,18.343 r0 top (schematic designator U3)
U4 "TPS7A4901" DGN0008D_L 77.6,46.45 r0 top
U5 "TPS7A3001" DGN0008D_L 78.025,53.95 r0 top
VSIN_I "BNC" BNC-TYCO_1-1337542-0 6,38.333 r180 top
VSIN_Q "BNC" BNC-TYCO_1-1337542-0 6,61.667 r180 top

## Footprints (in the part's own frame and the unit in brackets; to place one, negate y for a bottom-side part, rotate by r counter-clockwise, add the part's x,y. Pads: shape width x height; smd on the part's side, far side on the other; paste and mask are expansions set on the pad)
0603_C [mm]
  rect 0.93x0.98 smd: 1(-0.77,0) 2(0.77,0)
  silkscreen extent -1.53,-0.79 1.54,0.79, body extent -0.8,-0.4 0.8,0.4, height 0.3
0603_R [mm]
  rect 0.93x0.98 smd: 1(-0.77,0) 2(0.77,0)
  silkscreen extent -1.53,-0.79 1.54,0.79, body extent -0.85,-0.4 0.85,0.4, height 0.56
0805_C [mm]
  rect 1.16x1.47 smd: 1(-0.89,0) 2(0.89,0)
  silkscreen extent -1.77,-1.04 1.77,1.04, body extent -1,-0.62 1,0.63, height 0.77
0805_L [mm]
  rect 1.16x1.47 smd: 1(-0.89,0) 2(0.89,0)
  silkscreen extent -1.77,-1.04 1.77,1.03, body extent -1,-0.63 1,0.63, height 0.49
1206_C [mm]
  rect 1.13x1.8 smd: 1(-1.49,0) 2(1.49,0)
  silkscreen extent -2.36,-1.2 2.35,1.2, body extent -1.6,-0.81 1.6,0.79, height 1
BNC-TYCO_1-1337542-0 [mm] "BNC-50 Ohms  BNC Elbow PCB Socket With Mounting Posts"
  round 1.6 hole 0.9: 1(-5.48,0) MH(-5.48,2.54)
  round 2.7 hole 2: MH(-0.4,5.08) MH(-0.4,-5.08)
  silkscreen extent -7.5,-7.35 28,7.35, body extent -7.5,-7.35 28,7.35, height 13.16
DGN0008D_L [mm] "TSOP, 8-Leads, Body 3.1x3.1mm, Pitch 0.65mm, Thermal Pad 1.89x1.57mm, IPC High Density"
  rrect22% 1.15x0.45 smd: 1(-2.125,0.975) 2(-2.125,0.325) 3(-2.125,-0.325) 4(-2.125,-0.975) 5(2.125,-0.975) 6(2.125,-0.325) 7(2.125,0.325) 8(2.125,0.975)
  rrect6% 1.57x1.89 smd: 9(0,0)
  silkscreen extent -2.25,-1.55 1.15,1.87, body extent -2.45,-1.5 2.45,1.5, height 0.94
FP-R-8-IPC_A [mm]
  rect 2.474x0.622 smd paste+0 mask+0: 1(-2.416,1.905)
  rrect100% 2.474x0.622 smd paste+0 mask+0: 2(-2.416,0.635) 3(-2.416,-0.635) 4(-2.416,-1.905) 5(2.416,-1.905) 6(2.416,-0.635) 7(2.416,0.635) 8(2.416,1.905)
  silkscreen extent -4.8,-2.45 0.68,2.45, body extent -4.15,-2.95 4.15,2.95, height 0.25
MR30PW-M [mm]
  round 2.5 hole 1.7: 1(0,0) 2(3.5,0) 3(7,0)
  round 2 hole 1: MACH(-3,-10) MACH(10,-10)
  body extent -4.2,-13 11.2,0.95, height 5.05
"Pin HDR2X5/2.54mm-S" [mm] "Connector; Header; 5x2 Position"
  rect 1.5x1.5 hole 0.9: 1(0,0)
  round 1.5 hole 0.9: 2(0,2.54) 3(2.54,0) 4(2.54,2.54) 5(5.08,0) 6(5.08,2.54) 7(7.62,0) 8(7.62,2.54) 9(10.16,0) 10(10.16,2.54)
  silkscreen extent -1.27,-1.27 11.43,3.81, body extent -1.27,-1.27 11.43,3.81, height 7.58
PWP0020D_M [mm] "SOP, 20-Leads, Body 4.5x6.6mm, Pitch 0.65mm, Thermal Pad 2x3mm, IPC Low Density"
  rrect22% 1.6x0.45 smd: 1(-3.05,2.925) 2(-3.05,2.275) 3(-3.05,1.625) 4(-3.05,0.975) 5(-3.05,0.325) 6(-3.05,-0.325) 7(-3.05,-0.975) 8(-3.05,-1.625) 9(-3.05,-2.275) 10(-3.05,-2.925) 11(3.05,-2.925) 12(3.05,-2.275) 13(3.05,-1.625) 14(3.05,-0.975) 15(3.05,-0.325) 16(3.05,0.325) 17(3.05,0.975) 18(3.05,1.625) 19(3.05,2.275) 20(3.05,2.925)
  rrect5% 2x3 smd: 21(0,0)
  silkscreen extent -3.17,-3.3 1.85,3.82, body extent -3.21,-3.25 3.21,3.25, height 0.98
SOIC127P600X175-8M [mm] "SOIC, 8-Leads, Body 4.90x3.95mm, Pitch 1.27mm, IPC Low Density"
  oval 1.65x0.65 smd: 1(-2.825,1.905) 2(-2.825,0.635) 3(-2.825,-0.635) 4(-2.825,-1.905) 5(2.825,-1.905) 6(2.825,-0.635) 7(2.825,0.635) 8(2.825,1.905)
  silkscreen extent -2.95,-2.5 1.6,2.9, body extent -3,-2.5 3,2.5, height 1.75
SOT-23(SOT-23-3) [mm]
  rect 1.25x0.7 smd: 1(1.25,-0.95) 2(1.25,0.95) 3(-1.25,0)
  silkscreen extent -0.65,-1.46 0.9,1.46, body extent -1.5,-1.5 1.5,1.5, height 1.3

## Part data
C1_CH1 C1_CH2 C31_CH1 C31_CH2 C32_CH1 C32_CH2: library part "0805 100nF(104) 10% 50V", "贴片电容", Package=0805, SuppliersPartNumber=C49678
C2_CH1 C2_CH2 C3_CH1 C3_CH2 C5_AMP11 C5_AMP12 C7_AMP11 C7_AMP12 C10_MIXER11 C10_MIXER12 C10_MIXER21 C10_MIXER22 C12_MIXER11 C12_MIXER12 C12_MIXER21 C12_MIXER22 C14_PGA11 C14_PGA12 C16_PGA11 C16_PGA12 C23 C36: library part "0603 10nF (103) 10% 50V", "贴片电容", Package=0603, SuppliersPartNumber=C57112
C4_AMP11 C4_AMP12 C6_AMP11 C6_AMP12 C9_MIXER11 C9_MIXER12 C9_MIXER21 C9_MIXER22 C11_MIXER11 C11_MIXER12 C11_MIXER21 C11_MIXER22 C13_PGA11 C13_PGA12 C15_PGA11 C15_PGA12 C26 C33: library part "0603 100nF (104) 10% 50V", "贴片电容", Package=0603, SuppliersPartNumber=C14663
C8_AMP11 C8_AMP12: library part "0603 10pF (100) 5% 50V", "贴片电容", Package=0603, SuppliersPartNumber=C1634
C17 C18: library part "1206 100nF (104) 10% 50V", "贴片电容", Package=1206, SuppliersPartNumber=C24497
C19 C20 C21 C22 C24 C25 C27 C28 C29 C30 C34 C35: library part "0805 10uF (106) 10% 25V", "贴片电容", Package=0805, SuppliersPartNumber=C15850
CH1 CH1_I CH1_Q CH2 CH2_I CH2_Q VSIN_I VSIN_Q: "BNC-KE PIN 6.9mm distance", PartNumber=51K101-400A4
Q1_AMP11 Q1_AMP12 Q2_PGA11 Q2_PGA12 Q3_PGA11 Q3_PGA12 Q4_PGA11 Q4_PGA12 Q5_PGA11 Q5_PGA12: library part "2N7002 7002", "MOS(场效应管)", Package=SOT-23(SOT-23-3), SuppliersPartNumber=C8545
R1_CH1 R1_CH2 R2_CH1 R2_CH2 R5_AMP11 R5_AMP12 R10_PGA11 R10_PGA12 R11_PGA11 R11_PGA12 R12_PGA11 R12_PGA12 R13_PGA11 R13_PGA12 R14_PGA11 R14_PGA12 R15_PGA11 R15_PGA12 R16_PGA11 R16_PGA12 R17_PGA11 R17_PGA12 R21 R31 R33 R34 R43_CH1 R43_CH2 R44_CH1 R44_CH2 R45_CH1 R45_CH2: library part "0603 10KΩ (1002) 1%", "贴片电阻", Package=0603, SuppliersPartNumber=C25804
R3_AMP11 R3_AMP12 R8_PGA11 R8_PGA12 R9_PGA11 R9_PGA12: library part "0603 100Ω (1000) 1%", "贴片电阻", Package=0603, SuppliersPartNumber=C22775
R4_AMP11 R4_AMP12: library part "0603 910Ω (9100) 1%", "贴片电阻", Package=0603, SuppliersPartNumber=C23264
R6_MIXER11 R6_MIXER12 R6_MIXER21 R6_MIXER22: library part "0603 2KΩ (2001) 1%", "贴片电阻", Package=0603, SuppliersPartNumber=C22975
R7_MIXER11 R7_MIXER12 R7_MIXER21 R7_MIXER22 R41_MIXER11 R41_MIXER12 R41_MIXER21 R41_MIXER22 R42_MIXER11 R42_MIXER12 R42_MIXER21 R42_MIXER22: library part "0603 200Ω (2000) 1%", "贴片电阻", Package=0603, SuppliersPartNumber=C8218
R18 R19 R20 R22 R23 R24 R25 R26 R27 R28 R29 R30: library part "0603 49.9Ω (49R9) 1%", "贴片电阻", Package=0603, SuppliersPartNumber=C23185
R32 R35: library part "0603 91KΩ (9102) 1%", "贴片电阻", Package=0603, SuppliersPartNumber=C23265
U1_AMP11 U1_AMP12: "Wideband, Ultra-Low Noise, Voltage-Feedback OPERATIONAL AMPLIFIER with Shutdown"
U2_MIXER11 U2_MIXER12 U2_MIXER21 U2_MIXER22: library part CMP-09114-000033-1, "ANALOG MULTIPLIER OR DIVIDER, 25", Case/Package=SOIC, Dual Supply Voltage=5V, Max Dual Supply Voltage=5.5V, Max Frequency=250MHz, Max Input Voltage=1V, Max Operating Temperature=85°C, Max Power Dissipation=300mW, Min Dual Supply Voltage=4.5V, Min Operating Temperature=-40°C, Nominal Supply Current=16mA, Operating Supply Current=25mA, Output Voltage=2.5V, Package Quantity=1
U3_PGA11 U3_PGA12: library part CMP-0988-00128-2, "70-MHz High-Speed Programmable-Gain Amplifier, 0 to 70 degC, 20-pin SOP (PWP20), Green (RoHS & no Sb/Br)", Manufacturer="Texas Instruments"

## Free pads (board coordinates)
  round 4 hole 3.2: MACH(4,4) MACH(4,96) MACH(96,4) MACH(96,96)

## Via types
v1: diameter 0.45, hole 0.3, Top Layer to Bottom Layer, 208 vias
v2: diameter 0.5, hole 0.2, Top Layer to Bottom Layer, 12 vias
v3: diameter 0.5, hole 0.2, Top Layer to Bottom Layer, tented both sides, 10 vias

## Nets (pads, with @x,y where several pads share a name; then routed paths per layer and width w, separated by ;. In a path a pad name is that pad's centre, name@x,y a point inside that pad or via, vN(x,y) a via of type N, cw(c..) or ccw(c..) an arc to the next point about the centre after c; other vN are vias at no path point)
+AVDD_5P5V: C22.2 CH1_SET.1 CH1_SET.3 CH1_SET.5 CH1_SET.7 CH1_SET.9 CH2_SET.1 CH2_SET.3 CH2_SET.5 CH2_SET.7 CH2_SET.9 FB1_AMP11.1 FB1_AMP12.1 FB3_MIXER11.1 FB3_MIXER12.1 FB3_MIXER21.1 FB3_MIXER22.1 FB5_PGA11.1 FB5_PGA12.1 FB8.1 R10_PGA11.2 R10_PGA12.2 R12_PGA11.2 R12_PGA12.2 R14_PGA11.2 R14_PGA12.2 R16_PGA11.2 R16_PGA12.2 | length 47.9
  Bottom Layer w0.6: v1(35.305,82.887) 35.15,82.887 34.87,83.167 34.87,83.322 32.55,85.642 32.55,95.925 33.732,97.107 34.568,97.107 CH1_SET.9@34.717,97.255 CH1_SET.7@37.257,97.255 CH1_SET.5@39.797,97.255 CH1_SET.3@42.337,97.255 CH1_SET.1@44.877,97.255 ; v1(42.914,25.973) v1(46.381,25.973) v1(49.847,25.973) v1(53.314,25.973) ; v1(42.914,80.973) v1(46.381,80.973) v1(49.847,80.973) v1(53.314,80.973)
  other v1: 70.5,10.58 56.29,13.95 70.5,24.58 35.305,25.265 69,49.085 70.885,49.2 70.5,65.6 56.29,68.95 70.5,79.6
+AVEE_5P5V: C30.1 FB2_AMP11.1 FB2_AMP12.1 FB4_MIXER11.1 FB4_MIXER12.1 FB4_MIXER21.1 FB4_MIXER22.1 FB6_PGA11.1 FB6_PGA12.1 FB10.1
  other v1: 76.625,10.48 23.75,16.51 48.6,22.34 76.625,24.48 69.15,54.965 69.22,56.825 76.625,65.5 23.75,74.132 48.6,77.34 76.625,79.5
